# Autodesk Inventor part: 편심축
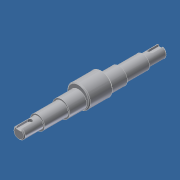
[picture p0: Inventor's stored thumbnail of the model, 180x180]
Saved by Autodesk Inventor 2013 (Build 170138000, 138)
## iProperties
Created: 2014-12
Part Number: 편심축
Material: 알루미늄 6061
Document SubType Name: Modeling
Designer: CAD-B31
Density: 2.71 g/cm^3
Mass: 90.367 g
Surface Area: 86.7923 cm^2
Volume: 33.3457 cm^3
Author: CAD-B31
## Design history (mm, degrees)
sketch "스케치1"
  geometry: L1 (-75.5, 0)-(75.5, 0); L2 (-75.5, 0)-(-75.5, 6); L3 (-75.5, 6)-(-55.5, 6); L4 (-55.5, 6)-(-55.5, 7.5); L5 (-55.5, 7.5)-(-30.5, 7.5); L6 (-30.5, 7.5)-(-30.5, 9); L7 (-30.5, 9)-(30.5, 9); L8 (30.5, 9)-(30.5, 7.5); L9 (30.5, 7.5)-(55.5, 7.5); L10 (55.5, 7.5)-(55.5, 6); L11 (55.5, 6)-(75.5, 6); L12 (75.5, 6)-(75.5, 0); L13 (-75.5, 6)-(-61.5, 6); L14 (-61.5, 6)-(-61.5, 3); L15 (-61.5, 3)-(-75.5, 3); L16 (-75.5, 3)-(-75.5, 6); L17 (61.5, 6)-(75.5, 6); L18 (75.5, 6)-(75.5, 3); L19 (75.5, 3)-(61.5, 3); L20 (61.5, 3)-(61.5, 6); 2 further points
  constraints: 40 end point, 11 parallel, 5 perpendicular, 3 horizontal, 2 midpoint, 1 coincident, 1 collinear, 1 point on line
  dimensions: "d0" = 151 distance of L1.start L1.end; "d2" = 12 diameter of L3 L1; "d3" = 12 diameter of L11 L1; "d4" = 15 diameter of L5 L1; "d5" = 15 diameter of L9 L1; "d6" = 18 diameter of L7 L1; "d7" = 20 distance of L2.end L3.end; "d8" = 25 distance of L4.end L5.end; "d9" = 20 distance of L10.end L11.end; "d10" = 25 distance of L8.end L9.end; "d11" = 3 distance of L19.end L17.start (derived); "d12" = 3 distance of L13.end L14.end; "d13" = 14 distance of L14.end L15.end; "d14" = 14 distance of L18.end L19.end
revolve "회전1" stored, may be unused: angle "d15" = 90 deg
extrude "돌출1" cut sketch "스케치1" stored distance "d16" = 5; taper "d17" = 0 deg
extrude "돌출2" cut sketch "스케치1" stored distance "d18" = 5; taper "d19" = 0 deg
fillet "모깎기1" dims "d20" = 2.5
sketch "스케치2"
  geometry: L1 (-12.5, 2)-(12.5, 2); L2 (-12.5, 2)-(-12.5, 14); L3 (-12.5, 14)-(12.5, 14); L4 (12.5, 14)-(12.5, 2); L5 (-30.5, -9)-(-30.5, 9) reference; L6 (30.5, -9)-(30.5, 9) reference; 1 further point
  constraints: 8 end point, 2 perpendicular, 1 horizontal, 1 parallel
  dimensions: "d21" = 2 distance from line of L1 point (0, 0); "d22" = 24 diameter of L3 L1; "d23" = 18 distance between parallel lines of L2 L5; "d24" = 18 distance between parallel lines of L6 L4
revolve "회전2" sketch "스케치2" stored, may be unused: angle "d25" = 90 deg
chamfer "모따기1" distance "d26" = 1; stored, may be unused: second distance "d27" = 2, angle "d28" = 45 deg
node "솔리드1"
